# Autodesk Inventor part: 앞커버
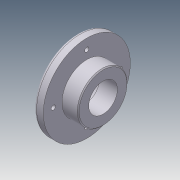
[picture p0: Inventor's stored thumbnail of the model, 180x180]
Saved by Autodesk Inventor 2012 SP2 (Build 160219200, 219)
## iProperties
Company: 한국ATC센터
Created: 2014-11
Part Number: 앞커버
Document SubType Name: Modeling
Designer: KYOUNG IL JANG
Density: 2.71 g/cm^3
Material: 알루미늄-6061
Mass: 204.895 g
Surface Area: 201.401 cm^2
Volume: 75.6071 cm^3
Author: KYOUNG IL JANG
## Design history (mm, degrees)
sketch "스케치1"
  geometry: L1 (-13.5, 0)-(13.5, 0); L2 (-13.5, 0)-(-13.5, 45.5); L3 (-13.5, 45.5)-(-3.5, 45.5); L4 (-3.5, 45.5)-(-3.5, 26); L5 (-3.5, 26)-(13.5, 26); L6 (13.5, 26)-(13.5, 0); 2 further points
  constraints: 12 end point, 3 parallel, 2 perpendicular, 1 coincident, 1 horizontal, 1 midpoint
  dimensions: "d0" = 27 distance of L1.start L1.end; "d1" = 91 diameter of L3 L1; "d2" = 52 diameter of L5 L1; "d3" = 10 distance of L2.end L3.end
revolve "회전1" sketch "스케치1" stored, may be unused: angle "d4" = 90 deg
hole "구멍1" diameter "d7" = 30; stored, may be unused: countersink angle "d11" = 90 deg, drill point angle "d13" = 118 deg; dims "d5" = 10, "d6" = 10, "d8" = 6, "d9" = 40, "d10" = 8.3, "d12" = 8
sketch "스케치2"
  geometry: 2 further points
  constraints: 1 vertical alignment
  dimensions: "d14" = 35 distance of point (0, 0) point (0, 35)
hole "구멍2" sketch "스케치2" at (0, 35) diameter "d15" = 4.5; stored, may be unused: countersink angle "d19" = 90 deg, drill point angle "d21" = 118 deg; dims "d16" = 6, "d17" = 8, "d18" = 4.4, "d20" = 8
chamfer "모따기1" distance "d25" = 0.8; stored, may be unused: second distance "d26" = 2, angle "d27" = 30 deg
fillet "모깎기1" dims "d28" = 0.3, "d29" = 3
chamfer "모따기2" distance "d30" = 1; stored, may be unused: second distance "d31" = 2, angle "d32" = 30 deg
node "솔리드1"
pattern_circular "원형 패턴1" dims angle "d23" = 360 deg
